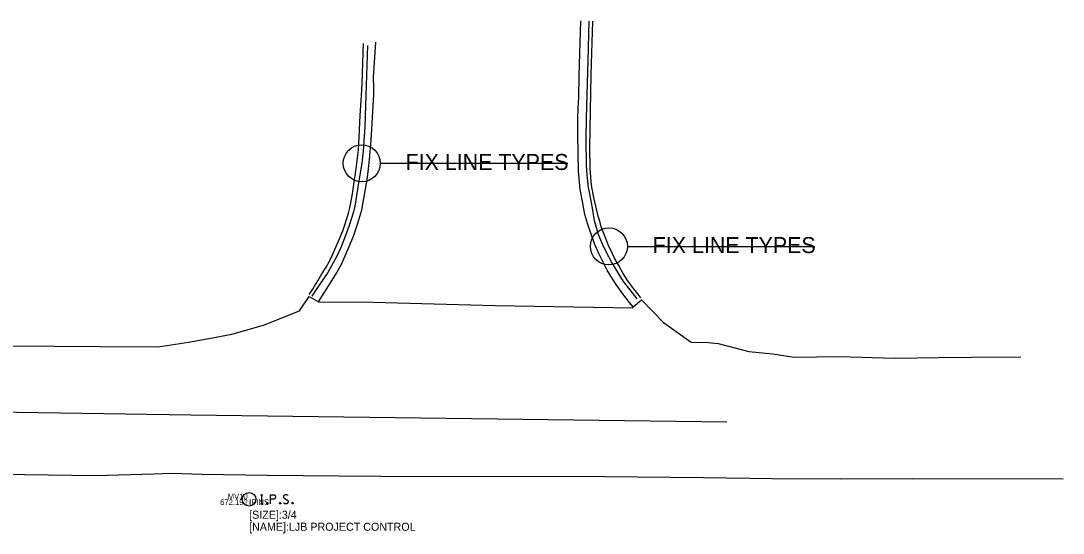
# Model space of a CAD drawing. Extents: x 1659932 to 1663108, y 619867 to 620611.
# Drawn here: x 1662925.7 to 1663108, y 620181.9 to 620271.5 of the extents above; entities that cross this region are included whole.
import ezdxf

# ---------------------------------------------------------------- set-up
doc = ezdxf.new("R2010")
doc.units = 0
for name, color, linetype in [('PM_X_CL_Dashed', 7, 'Continuous'), ('PV_X_Curb', 7, 'Continuous'), ('PV_X_EOP', 7, 'Continuous'), ('RS_Raster1', 7, 'Continuous'), ('SC_Scratch6', 7, 'Continuous'), ('SV_P_Mon_Cells_Set_Text', 7, 'Continuous'), ('SV_X_Text_Comment', 7, 'Continuous'), ('SV_X_Text_Elevation', 7, 'Continuous'), ('SV_X_Text_Name', 7, 'Continuous')]:
    doc.layers.add(name, color=color, linetype=linetype)

msp = doc.modelspace()

# ---------------------------------------------------------------- linework, layer by layer
at = {"layer": 'PM_X_CL_Dashed'}
msp.add_lwpolyline([(1661548.68, 620227.77), (1661669.96, 620225.42), (1661783.14, 620222.83), (1661893.22, 620220.99), (1661995.64, 620218.69), (1662098.65, 620216.83), (1662208.49, 620214.49), (1662310.47, 620212.73), (1662401.36, 620210.77), (1662501.77, 620209.17), (1662614.52, 620207.13), (1662727.83, 620205.67), (1662841.02, 620204.32), (1662955.43, 620202.56), (1663049.21, 620201.36)], dxfattribs=at)
at = {"layer": 'PV_X_Curb'}
for points in [[(1663033.5, 620222.84), (1663032.28, 620224.42), (1663031.12, 620225.88), (1663030.17, 620227.38), (1663029.01, 620229.34), (1663028.08, 620231.08), (1663027.38, 620232.56), (1663026.75, 620234.13), (1663026.03, 620236.49), (1663025.66, 620238.73), (1663025.19, 620241.22), (1663024.97, 620242.33), (1663024.72, 620244.57), (1663024.62, 620246.26), (1663024.55, 620250.8), (1663024.65, 620254.48), (1663024.74, 620258.61), (1663024.9, 620264.49), (1663025.08, 620271.42)], [(1663034.13, 620223.04), (1663033.59, 620223.73), (1663033.15, 620224.3), (1663032.68, 620224.91), (1663032.36, 620225.33), (1663031.89, 620225.98), (1663031.03, 620227.28), (1663030.26, 620228.66), (1663029.53, 620230), (1663028.99, 620231.12), (1663028.55, 620232.03), (1663028, 620233.43), (1663027.22, 620235.48), (1663026.94, 620236.45), (1663026.69, 620237.34), (1663025.9, 620240.59), (1663025.54, 620242.38), (1663025.43, 620243.4), (1663025.25, 620245.72), (1663025.21, 620249.16), (1663025.31, 620255.76), (1663025.43, 620262.11), (1663025.71, 620271.42)], [(1662976.11, 620223.6), (1662976.75, 620224.57), (1662977.05, 620225.09), (1662977.63, 620226.03), (1662978.34, 620227.23), (1662979.07, 620228.4), (1662979.63, 620229.35), (1662980.17, 620230.54), (1662980.8, 620231.89), (1662981.38, 620233.22), (1662981.98, 620234.73), (1662982.29, 620235.63), (1662982.68, 620236.89), (1662982.98, 620237.86), (1662983.17, 620238.56), (1662983.39, 620239.65), (1662983.69, 620241.25), (1662983.95, 620242.85), (1662984.34, 620245.67), (1662984.62, 620247.99), (1662984.71, 620248.94), (1662984.85, 620251.13), (1662985.05, 620254.93), (1662985.24, 620258.42), (1662985.37, 620260.41), (1662985.49, 620264.06), (1662985.57, 620265.98), (1662985.63, 620267.52)], [(1662986.33, 620267.18), (1662986.02, 620258.41), (1662985.86, 620253.03), (1662985.58, 620248.69), (1662985.31, 620246.57), (1662984.81, 620243.5), (1662984.09, 620239.09), (1662983.87, 620238.06), (1662983.12, 620235.71), (1662982.46, 620233.91), (1662981.73, 620231.96), (1662980.86, 620230.19), (1662979.4, 620227.46), (1662977.42, 620224.64), (1662976.58, 620223.3)]]:
    msp.add_lwpolyline(points, dxfattribs=at)
at = {"layer": 'PV_X_EOP'}
for points in [[(1663032.81, 620221.44), (1663032.13, 620222.24), (1663031.15, 620223.51), (1663029.91, 620225.21), (1663029.15, 620226.35), (1663028.27, 620227.89), (1663027.41, 620229.53), (1663026.79, 620230.81), (1663026.11, 620232.37), (1663025.42, 620234.16), (1663024.85, 620235.86), (1663024.36, 620237.63), (1663023.91, 620239.91), (1663023.52, 620241.96), (1663023.39, 620243.26), (1663023.21, 620245.19), (1663023.12, 620251.58), (1663023.13, 620254.29), (1663023.2, 620256.41), (1663023.28, 620257.96), (1663023.36, 620261.94), (1663023.61, 620271.49)], [(1662977.75, 620222.35), (1662979.53, 620225.17), (1662980.88, 620227.35), (1662981.78, 620228.91), (1662982.39, 620230.4), (1662983.11, 620232.01), (1662983.86, 620233.82), (1662984.61, 620236.11), (1662985.31, 620238.4), (1662985.47, 620239.4), (1662985.86, 620241.43), (1662986.23, 620243.68), (1662986.51, 620245.61), (1662986.65, 620247.23), (1662986.93, 620250.64), (1662987.4, 620258.59), (1662987.43, 620259.81), (1662987.38, 620261.61), (1662987.75, 620267.76)], [(1662923.53, 620214.61), (1662939.55, 620214.53), (1662949.7, 620214.45), (1662954.97, 620215.28), (1662959.17, 620216.06), (1662962.57, 620216.7), (1662968.1, 620218.24), (1662974.39, 620220.77), (1662976.1, 620223.29), (1662977.75, 620222.35), (1662987.31, 620222.29), (1663008.65, 620221.68), (1663032.65, 620221.3), (1663032.81, 620221.44), (1663034.26, 620222.71), (1663038.08, 620218.71), (1663042.97, 620215.3), (1663045.94, 620215.21), (1663047.68, 620215.07), (1663053.01, 620213.62), (1663057.25, 620213.21), (1663060.95, 620212.64), (1663068.79, 620212.74), (1663078.63, 620212.49), (1663086.25, 620212.57), (1663092.05, 620212.65), (1663100.61, 620212.68)], [(1662922.15, 620192.2), (1662938.72, 620191.92), (1662948.91, 620192.22), (1662952.12, 620192.38), (1662957.32, 620192.18), (1662968.76, 620192.03), (1662981.36, 620191.89), (1662995.92, 620191.78), (1663013.2, 620191.85), (1663027.79, 620191.76), (1663045.08, 620191.58), (1663057.15, 620191.4), (1663069.06, 620191.39), (1663081.65, 620191.4), (1663108.03, 620191.35)]]:
    msp.add_lwpolyline(points, dxfattribs=at)
at = {"layer": 'RS_Raster1'}
for points in [[(1662967.62, 620188.59), (1662967.97, 620188.59)], [(1662967.8, 620186.99), (1662967.8, 620188.59)], [(1662969.36, 620186.99), (1662969.36, 620188.59), (1662969.89, 620188.59), (1662969.94, 620188.57), (1662970.02, 620188.55), (1662970.06, 620188.52), (1662970.09, 620188.5), (1662970.13, 620188.43), (1662970.17, 620188.37), (1662970.19, 620188.27), (1662970.19, 620188.12), (1662970.18, 620188.07), (1662970.15, 620187.99), (1662970.11, 620187.91), (1662970.07, 620187.87), (1662970.03, 620187.84), (1662969.98, 620187.82), (1662969.89, 620187.8), (1662969.36, 620187.8)], [(1662972.37, 620188.47), (1662972.35, 620188.5), (1662972.31, 620188.52), (1662972.22, 620188.56), (1662972.09, 620188.59), (1662972.01, 620188.59), (1662971.97, 620188.59), (1662971.83, 620188.55), (1662971.71, 620188.47), (1662971.63, 620188.37), (1662971.61, 620188.27), (1662971.61, 620188.2), (1662971.63, 620188.09), (1662971.72, 620188.01), (1662972.33, 620187.63), (1662972.38, 620187.58), (1662972.4, 620187.53), (1662972.42, 620187.45), (1662972.42, 620187.38), (1662972.41, 620187.3), (1662972.4, 620187.25), (1662972.38, 620187.19), (1662972.36, 620187.14), (1662972.34, 620187.1), (1662972.3, 620187.06), (1662972.27, 620187.04), (1662972.23, 620187.01), (1662972.19, 620187), (1662972.09, 620186.99), (1662971.94, 620186.99), (1662971.84, 620187.01), (1662971.7, 620187.1), (1662971.61, 620187.17)], [(1662967.62, 620186.99), (1662967.97, 620186.99)], [(1662968.75, 620187.2), (1662968.81, 620187.2), (1662968.84, 620187.17), (1662968.88, 620187.12), (1662968.88, 620187.06), (1662968.84, 620187.01), (1662968.81, 620186.99), (1662968.75, 620186.99), (1662968.72, 620187.01), (1662968.69, 620187.06), (1662968.69, 620187.12), (1662968.72, 620187.17), (1662968.75, 620187.2)], [(1662971, 620187.2), (1662971.06, 620187.2), (1662971.09, 620187.17), (1662971.12, 620187.12), (1662971.12, 620187.06), (1662971.09, 620187.01), (1662971.06, 620186.99), (1662971, 620186.99), (1662970.97, 620187.01), (1662970.94, 620187.06), (1662970.94, 620187.12), (1662970.97, 620187.17), (1662971, 620187.2)], [(1662973.19, 620187.2), (1662973.24, 620187.2), (1662973.27, 620187.17), (1662973.31, 620187.12), (1662973.31, 620187.06), (1662973.27, 620187.01), (1662973.24, 620186.99), (1662973.19, 620186.99), (1662973.15, 620187.01), (1662973.12, 620187.06), (1662973.12, 620187.12), (1662973.15, 620187.17), (1662973.19, 620187.2)]]:
    msp.add_lwpolyline(points, dxfattribs=at)
msp.add_circle((1662965.6, 620187.78), 1.2, dxfattribs=at)
at = {"layer": 'SC_Scratch6'}
for p, q in [((1662988.55, 620246.57), (1663021.36, 620246.57)), ((1663031.79, 620232.03), (1663064.59, 620232.03))]:
    msp.add_line(p, q, dxfattribs=at)
for centre in [(1662985.31, 620246.57), (1663028.55, 620232.03)]:
    msp.add_circle(centre, 3.24, dxfattribs=at)

# ---------------------------------------------------------------- texts
for p in [(1662992.98, 620245.4), (1663036.22, 620230.86)]:
    msp.add_text('FIX LINE TYPES', height=2.8, dxfattribs=at).set_placement(p)
at = {"layer": 'SV_P_Mon_Cells_Set_Text'}
for s, p in [('[SIZE]:3/4', (1662965.6, 620184.38)), ('[NAME]:LJB PROJECT CONTROL', (1662965.6, 620182.28))]:
    msp.add_text(s, height=1.4, dxfattribs=at).set_placement(p)
at = {"layer": 'SV_X_Text_Comment'}
msp.add_text('IPINS', height=1, dxfattribs=at).set_placement((1662965.6, 620186.78))
at = {"layer": 'SV_X_Text_Elevation'}
msp.add_text('672.192', height=1, dxfattribs=at).set_placement((1662960.53, 620186.78))
at = {"layer": 'SV_X_Text_Name'}
msp.add_text('MV10', height=1, dxfattribs=at).set_placement((1662961.86, 620187.78))

doc.saveas('drawing.dxf')
